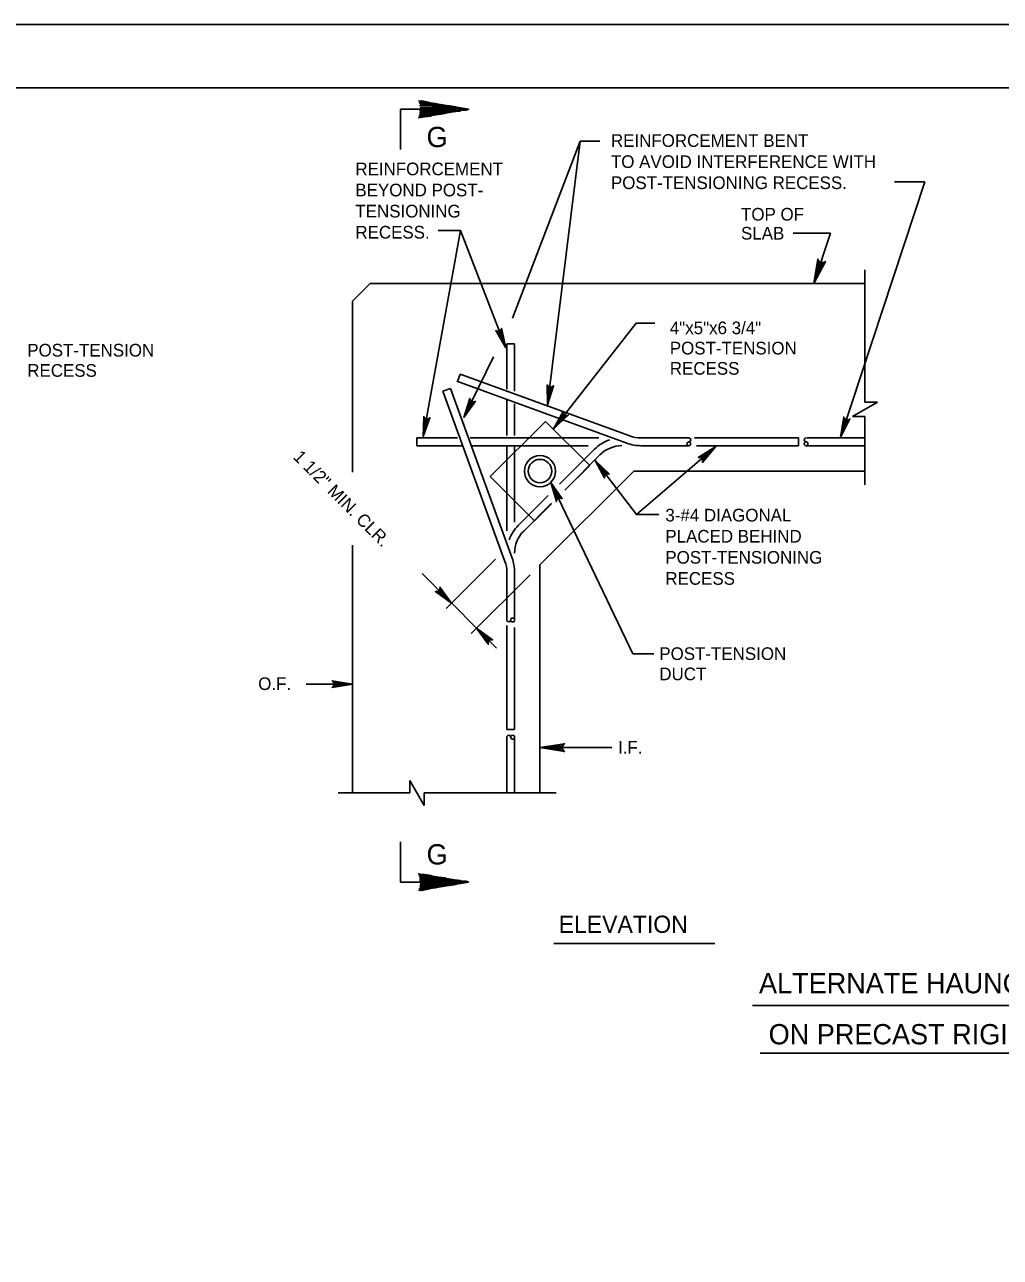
# Model space of a CAD drawing. Extents: x 641328 to 643024, y 298283 to 300065.
# Drawn here: x 642544.1 to 642775.4, y 299773.1 to 300065.3 of the extents above; entities that cross this region are included whole.
import ezdxf

# ---------------------------------------------------------------- set-up
doc = ezdxf.new("R2010")
doc.units = 0
for name, color, linetype in [('2', 7, 'Continuous'), ('63', 7, 'Continuous'), ('Default', 7, 'Continuous'), ('PLT-BNDY', 7, 'Continuous')]:
    doc.layers.add(name, color=color, linetype=linetype)

msp = doc.modelspace()

# ---------------------------------------------------------------- linework, layer by layer
at = {"layer": '2'}
for p, q in [((642208.51, 300050.3), (642994.5, 300050.3)), ((642633.18, 300045.28), (642633.18, 300035.69)), ((642633.18, 300045.28), (642648.21, 300045.28)), ((642757.53, 300028.03), (642737.51, 299967.47)), ((642735.16, 300015.85), (642731.22, 300003.92)), ((642689.13, 299949.18), (642707.98, 299965.29)), ((642610.8, 299908.99), (642621.83, 299908.99)), ((642633.18, 299862.02), (642633.18, 299871.62)), ((642633.18, 299862.02), (642648.21, 299862.02)), ((642707.72, 299847.49), (642669.55, 299847.49)), ((642718.46, 299821.51), (642825.55, 299821.51))]:
    msp.add_line(p, q, dxfattribs=at)
for points in [[(642637.48, 300047.21), (642649.36, 300045.23), (642637.48, 300043.25), (642637.68, 300043.45), (642638.87, 300043.45), (642640.45, 300043.64), (642637.68, 300043.64), (642637.88, 300044.04), (642642.24, 300044.04), (642643.82, 300044.24), (642637.88, 300044.24), (642637.88, 300044.63), (642645.4, 300044.63), (642647.38, 300044.83), (642637.88, 300044.83), (642637.88, 300045.03), (642648.77, 300045.03), (642649.36, 300045.23), (642647.78, 300045.43), (642638.08, 300045.43), (642637.88, 300045.62), (642646.39, 300045.82), (642644.81, 300046.02), (642637.88, 300046.02), (642637.88, 300046.22), (642643.23, 300046.22), (642641.44, 300046.61), (642637.88, 300046.61), (642637.68, 300046.81), (642640.06, 300046.81), (642638.28, 300047.21), (642637.68, 300047.01)], [(642733.61, 300008.96), (642733.17, 300008.89), (642731.22, 300003.92), (642733.61, 300008.96), (642733.93, 300009.16), (642731.22, 300003.92), (642732.64, 300009.06), (642732.32, 300009.37), (642731.22, 300003.92), (642732.16, 300009.74), (642732.32, 300009.37)], [(642657.07, 299993.06), (642656.83, 299992.79), (642658.15, 299988.73), (642657.07, 299993.06), (642657.17, 299993.34), (642658.15, 299988.73), (642656.42, 299992.63), (642656.07, 299992.66), (642658.15, 299988.73), (642655.78, 299992.8), (642656.07, 299992.66)], [(642669.26, 299979.51), (642668.92, 299979.39), (642668.07, 299975.2), (642669.26, 299979.51), (642669.48, 299979.7), (642668.07, 299975.2), (642668.47, 299979.45), (642668.18, 299979.65), (642668.07, 299975.2), (642668.01, 299979.92), (642668.18, 299979.65)], [(642650.68, 299975.93), (642650.32, 299975.92), (642648.23, 299972.2), (642650.68, 299975.93), (642650.95, 299976.05), (642648.23, 299972.2), (642649.91, 299976.12), (642649.7, 299976.4), (642648.23, 299972.2), (642649.61, 299976.7), (642649.7, 299976.4)], [(642672.67, 299972.64), (642672.31, 299972.7), (642669.5, 299969.49), (642672.67, 299972.64), (642672.96, 299972.7), (642669.5, 299969.49), (642671.96, 299972.98), (642671.81, 299973.29), (642669.5, 299969.49), (642671.79, 299973.61), (642671.81, 299973.29)], [(642639.95, 299971.95), (642639.6, 299971.84), (642638.61, 299967.69), (642639.95, 299971.95), (642640.18, 299972.14), (642638.61, 299967.69), (642639.16, 299971.92), (642638.88, 299972.13), (642638.61, 299967.69), (642638.71, 299972.4), (642638.88, 299972.13)], [(642739.51, 299971.67), (642739.14, 299971.61), (642737.51, 299967.47), (642739.51, 299971.67), (642739.77, 299971.83), (642737.51, 299967.47), (642738.69, 299971.75), (642738.43, 299972.01), (642737.51, 299967.47), (642738.3, 299972.32), (642738.43, 299972.01)], [(642704.09, 299962.73), (642704.44, 299962.59), (642707.98, 299965.29), (642704.09, 299962.73), (642703.78, 299962.73), (642707.98, 299965.29), (642704.75, 299962.24), (642704.84, 299961.88), (642707.98, 299965.29), (642704.79, 299961.55), (642704.84, 299961.88)], [(642681.57, 299958.16), (642681.72, 299958.48), (642679.32, 299962.02), (642681.57, 299958.16), (642681.55, 299957.86), (642679.32, 299962.02), (642682.08, 299958.76), (642682.42, 299958.83), (642679.32, 299962.02), (642682.74, 299958.77), (642682.42, 299958.83)], [(642670.23, 299952.56), (642670.45, 299952.85), (642668.82, 299956.8), (642670.23, 299952.56), (642670.16, 299952.27), (642668.82, 299956.8), (642670.85, 299953.05), (642671.2, 299953.04), (642668.82, 299956.8), (642671.5, 299952.92), (642671.2, 299953.04)], [(642642.58, 299931.7), (642642.47, 299931.35), (642645.32, 299928.17), (642642.58, 299931.7), (642642.56, 299932), (642645.32, 299928.17), (642642.16, 299931.04), (642641.82, 299930.92), (642645.32, 299928.17), (642641.5, 299930.94), (642641.82, 299930.92)], [(642653.97, 299918.73), (642654.08, 299919.08), (642651.23, 299922.26), (642653.97, 299918.73), (642653.99, 299918.44), (642651.23, 299922.26), (642654.39, 299919.4), (642654.73, 299919.51), (642651.23, 299922.26), (642655.05, 299919.49), (642654.73, 299919.51)], [(642617.22, 299908.41), (642617.39, 299908.75), (642621.83, 299908.99), (642617.22, 299908.41), (642616.99, 299908.21), (642621.83, 299908.99), (642617.4, 299909.21), (642617.23, 299909.54), (642621.83, 299908.99), (642616.99, 299909.76), (642617.23, 299909.54)], [(642671.81, 299893.24), (642671.6, 299893.64), (642666.27, 299893.93), (642671.81, 299893.24), (642672.09, 299892.99), (642666.27, 299893.93), (642671.6, 299894.2), (642671.79, 299894.59), (642666.27, 299893.93), (642672.09, 299894.86), (642671.79, 299894.59)], [(642637.48, 299860.1), (642649.36, 299862.08), (642637.48, 299864.06), (642637.68, 299863.86), (642638.87, 299863.86), (642640.45, 299863.66), (642637.68, 299863.66), (642637.88, 299863.27), (642642.24, 299863.27), (642643.82, 299863.07), (642637.88, 299863.07), (642637.88, 299862.67), (642645.4, 299862.67), (642647.38, 299862.47), (642637.88, 299862.47), (642637.88, 299862.28), (642648.77, 299862.28), (642649.36, 299862.08), (642647.78, 299861.88), (642638.08, 299861.88), (642637.88, 299861.68), (642646.39, 299861.48), (642644.81, 299861.29), (642637.88, 299861.29), (642637.88, 299861.09), (642643.23, 299861.09), (642641.44, 299860.69), (642637.88, 299860.69), (642637.68, 299860.49), (642640.06, 299860.49), (642638.28, 299860.1), (642637.68, 299860.3)]]:
    msp.add_lwpolyline(points, dxfattribs=at)
for radius in [7.87, 9.72]:
    msp.add_arc((642690.21, 299975.22), radius, 250, 270, dxfattribs=at)
for centre, major_axis in [((642701.56, 299965.96), (0.457, 0)), ((642729.36, 299965.96), (0.457, 0)), ((642659.8, 299924.19), (0, 0.457)), ((642659.8, 299896.4), (0, 0.457))]:
    msp.add_ellipse(centre, major_axis=major_axis, ratio=0.992474, dxfattribs=at)
for centre, major_axis, start_param, end_param in [((642701.53, 299966.89), (0.48, 0), 4.716665, 7.872006), ((642729.39, 299966.89), (0.48, 0), 1.552772, 4.708113), ((642658.87, 299924.23), (0, 0.48), 1.552772, 4.708113), ((642658.87, 299896.37), (0, 0.48), 4.716665, 7.872006)]:
    msp.add_ellipse(centre, major_axis=major_axis, ratio=0.992474, start_param=start_param, end_param=end_param, dxfattribs=at)
at = {"layer": 'Default'}
for p, q in [((642659.74, 299995.74), (642675.81, 300037.65)), ((642668.07, 299975.2), (642675.81, 300037.65)), ((642675.81, 300037.65), (642680.45, 300037.65)), ((642750.36, 300028.03), (642757.53, 300028.03)), ((642638.61, 299967.69), (642647.42, 300016.48)), ((642647.42, 300016.48), (642642.1, 300016.48)), ((642658.15, 299988.73), (642647.42, 300016.48)), ((642726.31, 300015.85), (642735.16, 300015.85)), ((642743.3, 300007.15), (642743.3, 299975.81)), ((642621.83, 299999.73), (642626.03, 300003.92)), ((642626.03, 300003.92), (642743.3, 300003.92)), ((642621.83, 299959.23), (642621.83, 299999.73)), ((642669.5, 299969.49), (642689.09, 299994.53)), ((642689.09, 299994.53), (642693.54, 299994.53)), ((642658.4, 299989.63), (642660.26, 299989.63)), ((642658.4, 299978.89), (642658.4, 299989.63)), ((642660.26, 299978.44), (642660.26, 299989.63)), ((642648.23, 299972.2), (642655.26, 299986.58)), ((642646.68, 299980.72), (642647.32, 299982.49)), ((642687.54, 299967.85), (642647.32, 299982.49)), ((642645.04, 299979.08), (642643.27, 299978.44)), ((642659.67, 299938.88), (642645.04, 299979.08)), ((642686.88, 299966.09), (642646.53, 299980.78)), ((642657.96, 299938.08), (642643.27, 299978.44)), ((642658.4, 299967.92), (642658.4, 299976.34)), ((642660.26, 299967.92), (642660.26, 299975.43)), ((642746.26, 299975.81), (642740.34, 299972.39)), ((642743.3, 299975.81), (642746.26, 299975.81)), ((642667.58, 299971.27), (642654.49, 299958.18)), ((642678.06, 299960.79), (642667.58, 299971.27)), ((642743.3, 299972.39), (642740.34, 299972.39)), ((642743.3, 299972.39), (642743.3, 299956.19)), ((642637.11, 299967.35), (642637.11, 299965.5)), ((642646.69, 299967.35), (642637.11, 299967.35)), ((642647.98, 299965.5), (642637.11, 299965.5)), ((642680.26, 299967.35), (642649.7, 299967.35)), ((642677.73, 299965.5), (642650.15, 299965.5)), ((642658.4, 299945.3), (642658.4, 299965.36)), ((642660.26, 299947.4), (642660.26, 299965.21)), ((642701.56, 299967.35), (642690.21, 299967.35)), ((642690.21, 299965.5), (642701.57, 299965.5)), ((642727.55, 299967.35), (642702.87, 299967.35)), ((642703.35, 299965.5), (642727.55, 299965.5)), ((642727.55, 299967.35), (642727.55, 299965.5)), ((642743.3, 299965.5), (642729.41, 299965.5)), ((642729.52, 299967.35), (642743.3, 299967.35)), ((642688.49, 299959.48), (642666.27, 299937.26)), ((642672.2, 299954.94), (642678.06, 299960.79)), ((642688.49, 299959.48), (642743.48, 299959.48)), ((642654.49, 299958.18), (642664.97, 299947.7)), ((642668.82, 299956.8), (642688.26, 299916.18)), ((642664.97, 299947.7), (642668.97, 299951.71)), ((642621.83, 299883.36), (642621.83, 299941.91)), ((642655.73, 299938.58), (642644.03, 299926.88)), ((642658.4, 299935.55), (642658.4, 299935.55)), ((642658.41, 299924.2), (642658.41, 299935.55)), ((642660.26, 299935.55), (642660.26, 299935.55)), ((642660.26, 299935.55), (642660.26, 299924.19)), ((642666.27, 299883.36), (642666.27, 299937.26)), ((642638.32, 299935.18), (642645.32, 299928.17)), ((642663.92, 299934.91), (642649.96, 299920.95)), ((642645.34, 299928.16), (642651.23, 299922.26)), ((642651.23, 299922.26), (642655.99, 299917.5)), ((642658.41, 299898.21), (642658.41, 299922.89)), ((642660.26, 299922.41), (642660.26, 299898.21)), ((642688.26, 299916.18), (642693.25, 299916.18)), ((642658.41, 299898.21), (642660.26, 299898.21)), ((642658.41, 299896.23), (642658.41, 299883.2)), ((642660.26, 299883.2), (642660.26, 299896.35)), ((642666.27, 299893.93), (642683.33, 299893.93)), ((642635.38, 299886.16), (642638.8, 299880.23)), ((642635.38, 299883.2), (642635.38, 299886.16)), ((642618.4, 299883.2), (642635.38, 299883.2)), ((642638.8, 299883.2), (642670.1, 299883.2)), ((642638.8, 299883.2), (642638.8, 299880.23)), ((642716.68, 299832.82), (642827.1, 299832.82))]:
    msp.add_line(p, q, dxfattribs=at)
for points in [[(642670.93, 299956.4), (642679.63, 299965.11)], [(642680.94, 299963.8), (642672.13, 299954.98)], [(642679.32, 299962.02), (642689.13, 299949.18), (642694.45, 299949.18)], [(642661.12, 299946.59), (642668.19, 299953.66)], [(642669.01, 299951.86), (642662.43, 299945.28)]]:
    msp.add_lwpolyline(points, dxfattribs=at)
for radius in [3.7, 2.78]:
    msp.add_circle((642666.27, 299959.48), radius, dxfattribs=at)
for centre, radius, start, end in [((642685.72, 299958.1), 9.26, 108.3873, 135), ((642685.72, 299958.1), 7.41, 90, 135), ((642667.66, 299940.04), 9.26, 135, 160.3163), ((642667.66, 299940.04), 7.41, 135, 180), ((642650.54, 299935.55), 9.72, 0, 20), ((642651, 299935.55), 7.41, 0, 20)]:
    msp.add_arc(centre, radius, start, end, dxfattribs=at)
at = {"layer": 'PLT-BNDY'}
msp.add_lwpolyline([(642168.51, 300065.3), (643009.51, 300065.3), (643009.51, 299471.3), (642168.51, 299471.3)], close=True, dxfattribs=at)

# ---------------------------------------------------------------- texts
at = {"layer": '2'}
for s, height, p in [('G', 4.8, (642639.38, 300036.27)), ('REINFORCEMENT BENT', 3, (642683.1, 300036.33)), ('TO AVOID INTERFERENCE WITH', 3, (642683.1, 300031.33)), ('POST-TENSIONING RECESS.', 3, (642683.1, 300026.33)), ('TOP OF', 3, (642713.94, 300018.86)), ('SLAB', 3, (642713.94, 300014.36)), ('4"x5"x6 3/4" ', 2.9999, (642697.06, 299991.93)), ('POST-TENSION', 2.9999, (642544.72, 299986.64)), ('POST-TENSION', 2.9999, (642697.06, 299987.13)), ('RECESS', 3, (642697.06, 299982.33)), ('RECESS', 3, (642544.72, 299981.84)), ('I.F.', 3, (642684.78, 299892.5)), ('G', 4.8, (642639.38, 299866.24)), ('ELEVATION', 4.08, (642670.7, 299850.03)), ('ALTERNATE HAUNCH DETAIL', 4.8, (642718.2, 299835.71)), ('ON PRECAST RIGID FRAME', 4.8, (642720.49, 299823.61))]:
    msp.add_text(s, height=height, dxfattribs=at).set_placement(p)
at = {"layer": '63'}
for s, height, p in [('POST-TENSION', 2.9999, (642694.57, 299914.71)), ('DUCT', 3, (642694.57, 299909.91)), ('O.F.', 3, (642599.47, 299907.59))]:
    msp.add_text(s, height=height, dxfattribs=at).set_placement(p)
at = {"layer": 'Default'}
for s, p in [('REINFORCEMENT ', (642622.51, 300029.6)), ('BEYOND POST- ', (642622.51, 300024.6)), ('TENSIONING ', (642622.51, 300019.6)), ('RECESS.', (642622.51, 300014.6)), ('3-#4 DIAGONAL', (642696, 299947.54)), ('PLACED BEHIND', (642696, 299942.54)), ('POST-TENSIONING ', (642696, 299937.54)), ('RECESS', (642696, 299932.54))]:
    msp.add_text(s, height=3, dxfattribs=at).set_placement(p)
msp.add_text('1 1/2" MIN. CLR.', height=3, rotation=315, dxfattribs=at).set_placement((642607.55, 299962.62))

doc.saveas('drawing.dxf')
